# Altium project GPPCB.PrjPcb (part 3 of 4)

## Sheet Protection.SchDoc: P.C. BOARD
size A2; Revision: A; SheetNumber: 0; SheetTotal: 0
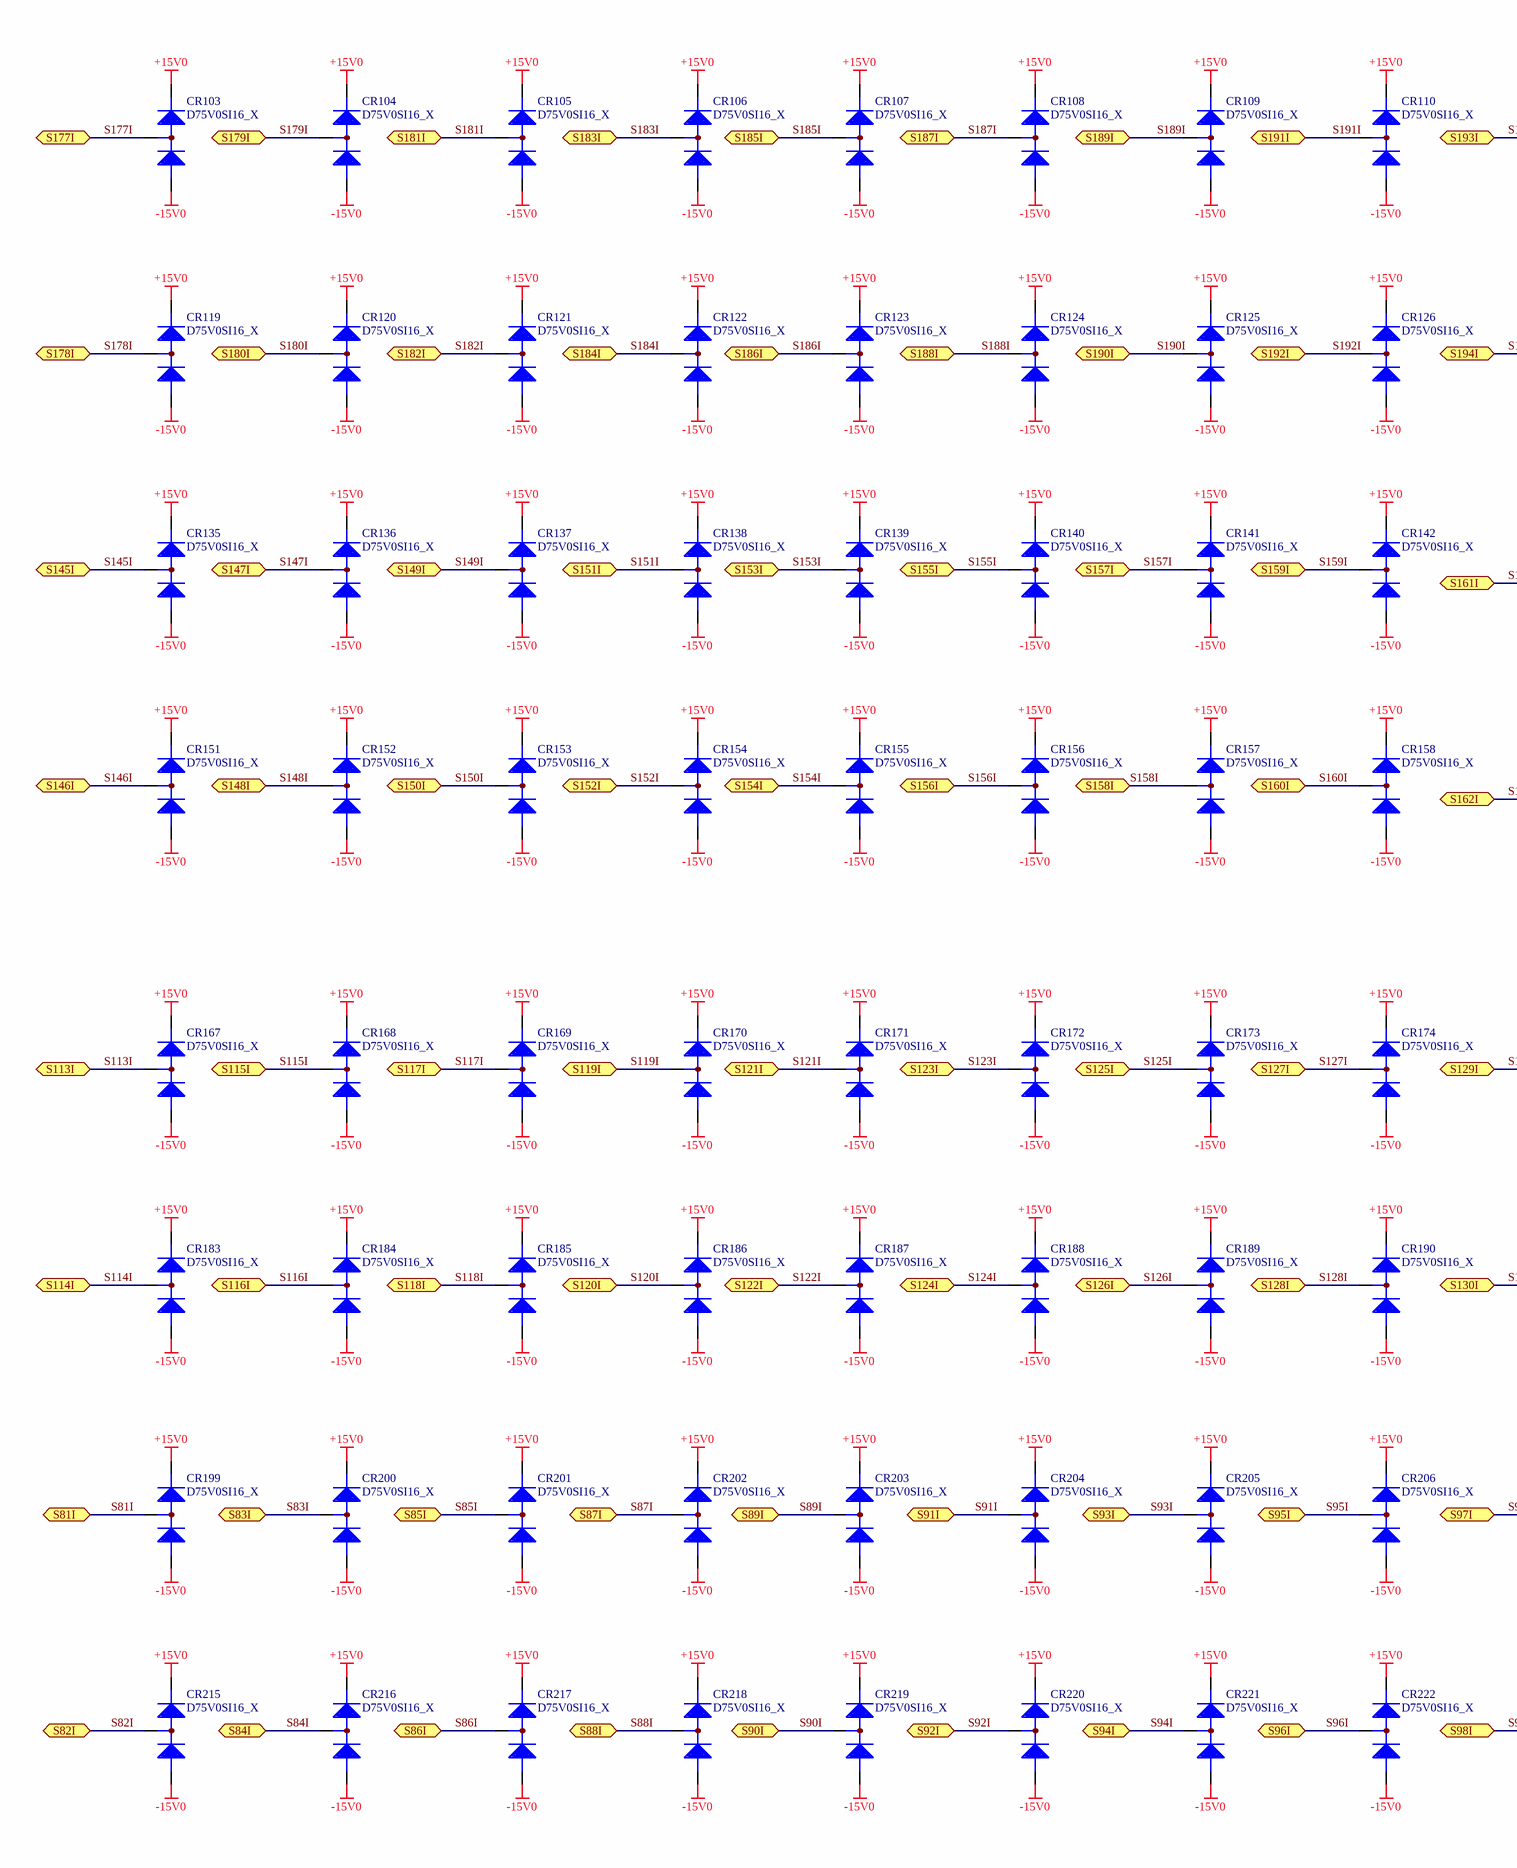
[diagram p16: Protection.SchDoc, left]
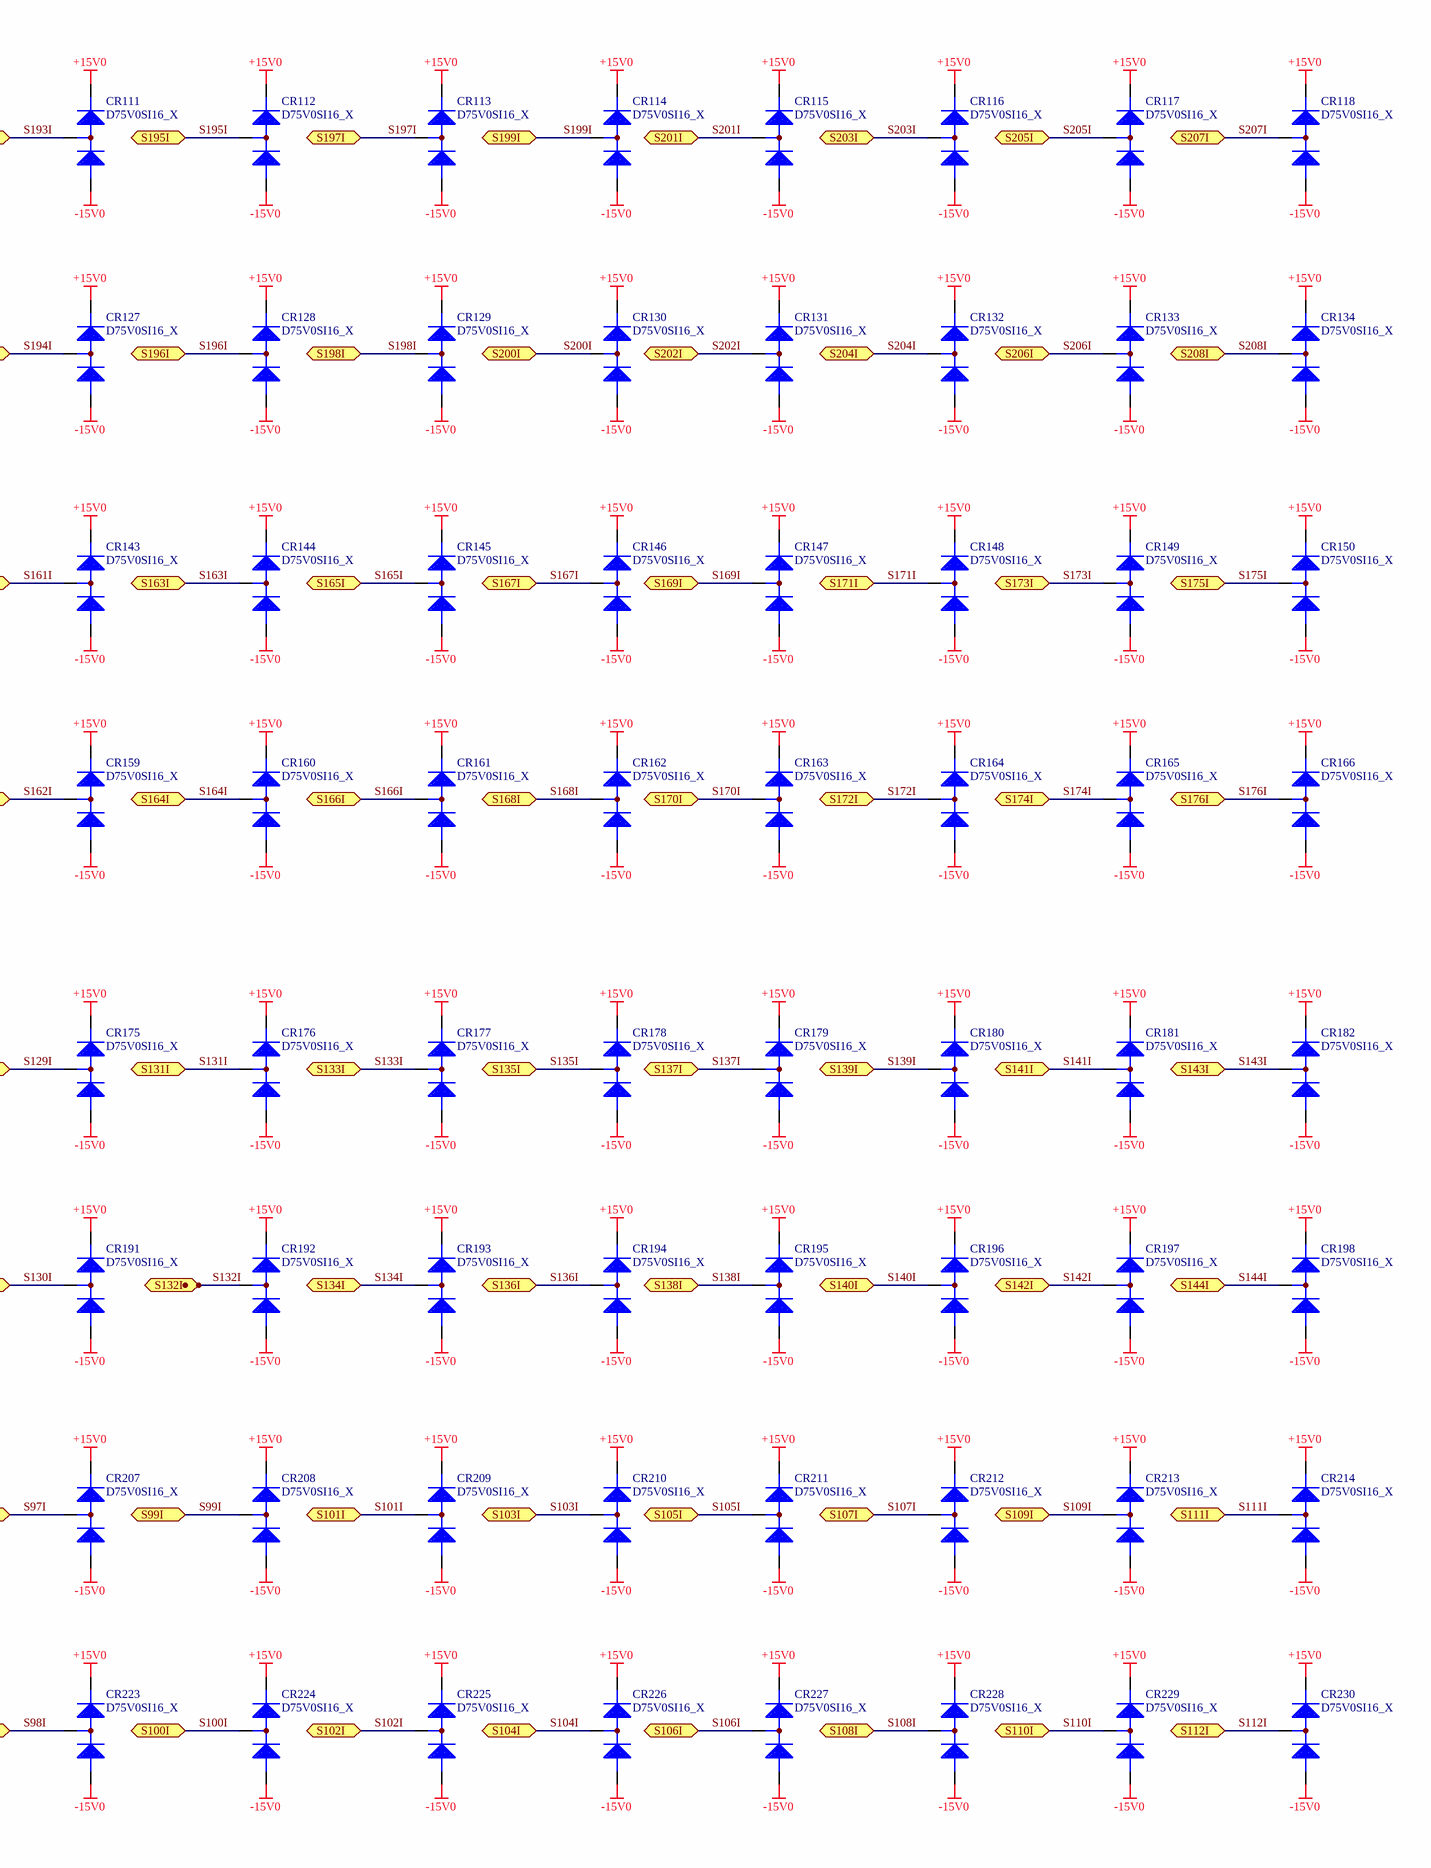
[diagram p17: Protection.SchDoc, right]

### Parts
CR103  D75V0SI16__X  [SOT-23/N]  (value not drawn)
CR104  D75V0SI16__X  [SOT-23/N]  (value not drawn)
CR105  D75V0SI16__X  [SOT-23/N]  (value not drawn)
CR106  D75V0SI16__X  [SOT-23/N]  (value not drawn)
CR107  D75V0SI16__X  [SOT-23/N]  (value not drawn)
CR108  D75V0SI16__X  [SOT-23/N]  (value not drawn)
CR109  D75V0SI16__X  [SOT-23/N]  (value not drawn)
CR110  D75V0SI16__X  [SOT-23/N]  (value not drawn)
CR111  D75V0SI16__X  [SOT-23/N]  (value not drawn)
CR112  D75V0SI16__X  [SOT-23/N]  (value not drawn)
CR113  D75V0SI16__X  [SOT-23/N]  (value not drawn)
CR114  D75V0SI16__X  [SOT-23/N]  (value not drawn)
CR115  D75V0SI16__X  [SOT-23/N]  (value not drawn)
CR116  D75V0SI16__X  [SOT-23/N]  (value not drawn)
CR117  D75V0SI16__X  [SOT-23/N]  (value not drawn)
CR118  D75V0SI16__X  [SOT-23/N]  (value not drawn)
CR119  D75V0SI16__X  [SOT-23/N]  (value not drawn)
CR120  D75V0SI16__X  [SOT-23/N]  (value not drawn)
CR121  D75V0SI16__X  [SOT-23/N]  (value not drawn)
CR122  D75V0SI16__X  [SOT-23/N]  (value not drawn)
CR123  D75V0SI16__X  [SOT-23/N]  (value not drawn)
CR124  D75V0SI16__X  [SOT-23/N]  (value not drawn)
CR125  D75V0SI16__X  [SOT-23/N]  (value not drawn)
CR126  D75V0SI16__X  [SOT-23/N]  (value not drawn)
CR127  D75V0SI16__X  [SOT-23/N]  (value not drawn)
CR128  D75V0SI16__X  [SOT-23/N]  (value not drawn)
CR129  D75V0SI16__X  [SOT-23/N]  (value not drawn)
CR130  D75V0SI16__X  [SOT-23/N]  (value not drawn)
CR131  D75V0SI16__X  [SOT-23/N]  (value not drawn)
CR132  D75V0SI16__X  [SOT-23/N]  (value not drawn)
CR133  D75V0SI16__X  [SOT-23/N]  (value not drawn)
CR134  D75V0SI16__X  [SOT-23/N]  (value not drawn)
CR135  D75V0SI16__X  [SOT-23/N]  (value not drawn)
CR136  D75V0SI16__X  [SOT-23/N]  (value not drawn)
CR137  D75V0SI16__X  [SOT-23/N]  (value not drawn)
CR138  D75V0SI16__X  [SOT-23/N]  (value not drawn)
CR139  D75V0SI16__X  [SOT-23/N]  (value not drawn)
CR140  D75V0SI16__X  [SOT-23/N]  (value not drawn)
CR141  D75V0SI16__X  [SOT-23/N]  (value not drawn)
CR142  D75V0SI16__X  [SOT-23/N]  (value not drawn)
CR143  D75V0SI16__X  [SOT-23/N]  (value not drawn)
CR144  D75V0SI16__X  [SOT-23/N]  (value not drawn)
CR145  D75V0SI16__X  [SOT-23/N]  (value not drawn)
CR146  D75V0SI16__X  [SOT-23/N]  (value not drawn)
CR147  D75V0SI16__X  [SOT-23/N]  (value not drawn)
CR148  D75V0SI16__X  [SOT-23/N]  (value not drawn)
CR149  D75V0SI16__X  [SOT-23/N]  (value not drawn)
CR150  D75V0SI16__X  [SOT-23/N]  (value not drawn)
CR151  D75V0SI16__X  [SOT-23/N]  (value not drawn)
CR152  D75V0SI16__X  [SOT-23/N]  (value not drawn)
CR153  D75V0SI16__X  [SOT-23/N]  (value not drawn)
CR154  D75V0SI16__X  [SOT-23/N]  (value not drawn)
CR155  D75V0SI16__X  [SOT-23/N]  (value not drawn)
CR156  D75V0SI16__X  [SOT-23/N]  (value not drawn)
CR157  D75V0SI16__X  [SOT-23/N]  (value not drawn)
CR158  D75V0SI16__X  [SOT-23/N]  (value not drawn)
CR159  D75V0SI16__X  [SOT-23/N]  (value not drawn)
CR160  D75V0SI16__X  [SOT-23/N]  (value not drawn)
CR161  D75V0SI16__X  [SOT-23/N]  (value not drawn)
CR162  D75V0SI16__X  [SOT-23/N]  (value not drawn)
CR163  D75V0SI16__X  [SOT-23/N]  (value not drawn)
CR164  D75V0SI16__X  [SOT-23/N]  (value not drawn)
CR165  D75V0SI16__X  [SOT-23/N]  (value not drawn)
CR166  D75V0SI16__X  [SOT-23/N]  (value not drawn)
CR167  D75V0SI16__X  [SOT-23/N]  (value not drawn)
CR168  D75V0SI16__X  [SOT-23/N]  (value not drawn)
CR169  D75V0SI16__X  [SOT-23/N]  (value not drawn)
CR170  D75V0SI16__X  [SOT-23/N]  (value not drawn)
CR171  D75V0SI16__X  [SOT-23/N]  (value not drawn)
CR172  D75V0SI16__X  [SOT-23/N]  (value not drawn)
CR173  D75V0SI16__X  [SOT-23/N]  (value not drawn)
CR174  D75V0SI16__X  [SOT-23/N]  (value not drawn)
CR175  D75V0SI16__X  [SOT-23/N]  (value not drawn)
CR176  D75V0SI16__X  [SOT-23/N]  (value not drawn)
CR177  D75V0SI16__X  [SOT-23/N]  (value not drawn)
CR178  D75V0SI16__X  [SOT-23/N]  (value not drawn)
CR179  D75V0SI16__X  [SOT-23/N]  (value not drawn)
CR180  D75V0SI16__X  [SOT-23/N]  (value not drawn)
CR181  D75V0SI16__X  [SOT-23/N]  (value not drawn)
CR182  D75V0SI16__X  [SOT-23/N]  (value not drawn)
CR183  D75V0SI16__X  [SOT-23/N]  (value not drawn)
CR184  D75V0SI16__X  [SOT-23/N]  (value not drawn)
CR185  D75V0SI16__X  [SOT-23/N]  (value not drawn)
CR186  D75V0SI16__X  [SOT-23/N]  (value not drawn)
CR187  D75V0SI16__X  [SOT-23/N]  (value not drawn)
CR188  D75V0SI16__X  [SOT-23/N]  (value not drawn)
CR189  D75V0SI16__X  [SOT-23/N]  (value not drawn)
CR190  D75V0SI16__X  [SOT-23/N]  (value not drawn)
CR191  D75V0SI16__X  [SOT-23/N]  (value not drawn)
CR192  D75V0SI16__X  [SOT-23/N]  (value not drawn)
CR193  D75V0SI16__X  [SOT-23/N]  (value not drawn)
CR194  D75V0SI16__X  [SOT-23/N]  (value not drawn)
CR195  D75V0SI16__X  [SOT-23/N]  (value not drawn)
CR196  D75V0SI16__X  [SOT-23/N]  (value not drawn)
CR197  D75V0SI16__X  [SOT-23/N]  (value not drawn)
CR198  D75V0SI16__X  [SOT-23/N]  (value not drawn)
CR199  D75V0SI16__X  [SOT-23/N]  (value not drawn)
CR200  D75V0SI16__X  [SOT-23/N]  (value not drawn)
CR201  D75V0SI16__X  [SOT-23/N]  (value not drawn)
CR202  D75V0SI16__X  [SOT-23/N]  (value not drawn)
CR203  D75V0SI16__X  [SOT-23/N]  (value not drawn)
CR204  D75V0SI16__X  [SOT-23/N]  (value not drawn)
CR205  D75V0SI16__X  [SOT-23/N]  (value not drawn)
CR206  D75V0SI16__X  [SOT-23/N]  (value not drawn)
CR207  D75V0SI16__X  [SOT-23/N]  (value not drawn)
CR208  D75V0SI16__X  [SOT-23/N]  (value not drawn)
CR209  D75V0SI16__X  [SOT-23/N]  (value not drawn)
CR210  D75V0SI16__X  [SOT-23/N]  (value not drawn)
CR211  D75V0SI16__X  [SOT-23/N]  (value not drawn)
CR212  D75V0SI16__X  [SOT-23/N]  (value not drawn)
CR213  D75V0SI16__X  [SOT-23/N]  (value not drawn)
CR214  D75V0SI16__X  [SOT-23/N]  (value not drawn)
CR215  D75V0SI16__X  [SOT-23/N]  (value not drawn)
CR216  D75V0SI16__X  [SOT-23/N]  (value not drawn)
CR217  D75V0SI16__X  [SOT-23/N]  (value not drawn)
CR218  D75V0SI16__X  [SOT-23/N]  (value not drawn)
CR219  D75V0SI16__X  [SOT-23/N]  (value not drawn)
CR220  D75V0SI16__X  [SOT-23/N]  (value not drawn)
CR221  D75V0SI16__X  [SOT-23/N]  (value not drawn)
CR222  D75V0SI16__X  [SOT-23/N]  (value not drawn)
CR223  D75V0SI16__X  [SOT-23/N]  (value not drawn)
CR224  D75V0SI16__X  [SOT-23/N]  (value not drawn)
CR225  D75V0SI16__X  [SOT-23/N]  (value not drawn)
CR226  D75V0SI16__X  [SOT-23/N]  (value not drawn)
CR227  D75V0SI16__X  [SOT-23/N]  (value not drawn)
CR228  D75V0SI16__X  [SOT-23/N]  (value not drawn)
CR229  D75V0SI16__X  [SOT-23/N]  (value not drawn)
CR230  D75V0SI16__X  [SOT-23/N]  (value not drawn)

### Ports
S81I (bidir), S82I (bidir), S83I (bidir), S84I (bidir), S85I (bidir), S86I (bidir), S87I (bidir), S88I (bidir), S89I (bidir), S90I (bidir), S91I (bidir), S92I (bidir), S93I (bidir), S94I (bidir), S95I (bidir), S96I (bidir), S97I (bidir), S98I (bidir), S99I (bidir), S100I (bidir), S101I (bidir), S102I (bidir), S103I (bidir), S104I (bidir), S105I (bidir), S106I (bidir), S107I (bidir), S108I (bidir), S109I (bidir), S110I (bidir), S111I (bidir), S112I (bidir), S113I (bidir), S114I (bidir), S115I (bidir), S116I (bidir), S117I (bidir), S118I (bidir), S119I (bidir), S120I (bidir), S121I (bidir), S122I (bidir), S123I (bidir), S124I (bidir), S125I (bidir), S126I (bidir), S127I (bidir), S128I (bidir), S129I (bidir), S130I (bidir), S131I (bidir), S132I (bidir), S133I (bidir), S134I (bidir), S135I (bidir), S136I (bidir), S137I (bidir), S138I (bidir), S139I (bidir), S140I (bidir), S141I (bidir), S142I (bidir), S143I (bidir), S144I (bidir), S145I (bidir), S146I (bidir), S147I (bidir), S148I (bidir), S149I (bidir), S150I (bidir), S151I (bidir), S152I (bidir), S153I (bidir), S154I (bidir), S155I (bidir), S156I (bidir), S157I (bidir), S158I (bidir), S159I (bidir), S160I (bidir), S161I (bidir), S162I (bidir), S163I (bidir), S164I (bidir), S165I (bidir), S166I (bidir), S167I (bidir), S168I (bidir), S169I (bidir), S170I (bidir), S171I (bidir), S172I (bidir), S173I (bidir), S174I (bidir), S175I (bidir), S176I (bidir), S177I (bidir), S178I (bidir), S179I (bidir), S180I (bidir), S181I (bidir), S182I (bidir), S183I (bidir), S184I (bidir), S185I (bidir), S186I (bidir), S187I (bidir), S188I (bidir), S189I (bidir), S190I (bidir), S191I (bidir), S192I (bidir), S193I (bidir), S194I (bidir), S195I (bidir), S196I (bidir), S197I (bidir), S198I (bidir), S199I (bidir), S200I (bidir), S201I (bidir), S202I (bidir), S203I (bidir), S204I (bidir), S205I (bidir), S206I (bidir), S207I (bidir), S208I (bidir)

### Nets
+15V0: CR103.2(K) CR104.2(K) CR105.2(K) CR106.2(K) CR107.2(K) CR108.2(K) CR109.2(K) CR110.2(K) CR111.2(K) CR112.2(K) CR113.2(K) CR114.2(K) CR115.2(K) CR116.2(K) CR117.2(K) CR118.2(K) CR119.2(K) CR120.2(K) CR121.2(K) CR122.2(K) CR123.2(K) CR124.2(K) CR125.2(K) CR126.2(K) CR127.2(K) CR128.2(K) CR129.2(K) CR130.2(K) CR131.2(K) CR132.2(K) CR133.2(K) CR134.2(K) CR135.2(K) CR136.2(K) CR137.2(K) CR138.2(K) CR139.2(K) CR140.2(K) CR141.2(K) CR142.2(K) CR143.2(K) CR144.2(K) CR145.2(K) CR146.2(K) CR147.2(K) CR148.2(K) CR149.2(K) CR150.2(K) CR151.2(K) CR152.2(K) CR153.2(K) CR154.2(K) CR155.2(K) CR156.2(K) CR157.2(K) CR158.2(K) CR159.2(K) CR160.2(K) CR161.2(K) CR162.2(K) CR163.2(K) CR164.2(K) CR165.2(K) CR166.2(K) CR167.2(K) CR168.2(K) CR169.2(K) CR170.2(K) CR171.2(K) CR172.2(K) CR173.2(K) CR174.2(K) CR175.2(K) CR176.2(K) CR177.2(K) CR178.2(K) CR179.2(K) CR180.2(K) CR181.2(K) CR182.2(K) CR183.2(K) CR184.2(K) CR185.2(K) CR186.2(K) CR187.2(K) CR188.2(K) CR189.2(K) CR190.2(K) CR191.2(K) CR192.2(K) CR193.2(K) CR194.2(K) CR195.2(K) CR196.2(K) CR197.2(K) CR198.2(K) CR199.2(K) CR200.2(K) CR201.2(K) CR202.2(K) CR203.2(K) CR204.2(K) CR205.2(K) CR206.2(K) CR207.2(K) CR208.2(K) CR209.2(K) CR210.2(K) CR211.2(K) CR212.2(K) CR213.2(K) CR214.2(K) CR215.2(K) CR216.2(K) CR217.2(K) CR218.2(K) CR219.2(K) CR220.2(K) CR221.2(K) CR222.2(K) CR223.2(K) CR224.2(K) CR225.2(K) CR226.2(K) CR227.2(K) CR228.2(K) CR229.2(K) CR230.2(K)
-15V0: CR103.1(A) CR104.1(A) CR105.1(A) CR106.1(A) CR107.1(A) CR108.1(A) CR109.1(A) CR110.1(A) CR111.1(A) CR112.1(A) CR113.1(A) CR114.1(A) CR115.1(A) CR116.1(A) CR117.1(A) CR118.1(A) CR119.1(A) CR120.1(A) CR121.1(A) CR122.1(A) CR123.1(A) CR124.1(A) CR125.1(A) CR126.1(A) CR127.1(A) CR128.1(A) CR129.1(A) CR130.1(A) CR131.1(A) CR132.1(A) CR133.1(A) CR134.1(A) CR135.1(A) CR136.1(A) CR137.1(A) CR138.1(A) CR139.1(A) CR140.1(A) CR141.1(A) CR142.1(A) CR143.1(A) CR144.1(A) CR145.1(A) CR146.1(A) CR147.1(A) CR148.1(A) CR149.1(A) CR150.1(A) CR151.1(A) CR152.1(A) CR153.1(A) CR154.1(A) CR155.1(A) CR156.1(A) CR157.1(A) CR158.1(A) CR159.1(A) CR160.1(A) CR161.1(A) CR162.1(A) CR163.1(A) CR164.1(A) CR165.1(A) CR166.1(A) CR167.1(A) CR168.1(A) CR169.1(A) CR170.1(A) CR171.1(A) CR172.1(A) CR173.1(A) CR174.1(A) CR175.1(A) CR176.1(A) CR177.1(A) CR178.1(A) CR179.1(A) CR180.1(A) CR181.1(A) CR182.1(A) CR183.1(A) CR184.1(A) CR185.1(A) CR186.1(A) CR187.1(A) CR188.1(A) CR189.1(A) CR190.1(A) CR191.1(A) CR192.1(A) CR193.1(A) CR194.1(A) CR195.1(A) CR196.1(A) CR197.1(A) CR198.1(A) CR199.1(A) CR200.1(A) CR201.1(A) CR202.1(A) CR203.1(A) CR204.1(A) CR205.1(A) CR206.1(A) CR207.1(A) CR208.1(A) CR209.1(A) CR210.1(A) CR211.1(A) CR212.1(A) CR213.1(A) CR214.1(A) CR215.1(A) CR216.1(A) CR217.1(A) CR218.1(A) CR219.1(A) CR220.1(A) CR221.1(A) CR222.1(A) CR223.1(A) CR224.1(A) CR225.1(A) CR226.1(A) CR227.1(A) CR228.1(A) CR229.1(A) CR230.1(A)
S81I: CR199.3(KA) ; port S81I
S82I: CR215.3(KA) ; port S82I
S83I: CR200.3(KA) ; port S83I
S84I: CR216.3(KA) ; port S84I
S85I: CR201.3(KA) ; port S85I
S86I: CR217.3(KA) ; port S86I
S87I: CR202.3(KA) ; port S87I
S88I: CR218.3(KA) ; port S88I
S89I: CR203.3(KA) ; port S89I
S90I: CR219.3(KA) ; port S90I
S91I: CR204.3(KA) ; port S91I
S92I: CR220.3(KA) ; port S92I
S93I: CR205.3(KA) ; port S93I
S94I: CR221.3(KA) ; port S94I
S95I: CR206.3(KA) ; port S95I
S96I: CR222.3(KA) ; port S96I
S97I: CR207.3(KA) ; port S97I
S98I: CR223.3(KA) ; port S98I
S99I: CR208.3(KA) ; port S99I
S100I: CR224.3(KA) ; port S100I
S101I: CR209.3(KA) ; port S101I
S102I: CR225.3(KA) ; port S102I
S103I: CR210.3(KA) ; port S103I
S104I: CR226.3(KA) ; port S104I
S105I: CR211.3(KA) ; port S105I
S106I: CR227.3(KA) ; port S106I
S107I: CR212.3(KA) ; port S107I
S108I: CR228.3(KA) ; port S108I
S109I: CR213.3(KA) ; port S109I
S110I: CR229.3(KA) ; port S110I
S111I: CR214.3(KA) ; port S111I
S112I: CR230.3(KA) ; port S112I
S113I: CR167.3(KA) ; port S113I
S114I: CR183.3(KA) ; port S114I
S115I: CR168.3(KA) ; port S115I
S116I: CR184.3(KA) ; port S116I
S117I: CR169.3(KA) ; port S117I
S118I: CR185.3(KA) ; port S118I
S119I: CR170.3(KA) ; port S119I
S120I: CR186.3(KA) ; port S120I
S121I: CR171.3(KA) ; port S121I
S122I: CR187.3(KA) ; port S122I
S123I: CR172.3(KA) ; port S123I
S124I: CR188.3(KA) ; port S124I
S125I: CR173.3(KA) ; port S125I
S126I: CR189.3(KA) ; port S126I
S127I: CR174.3(KA) ; port S127I
S128I: CR190.3(KA) ; port S128I
S129I: CR175.3(KA) ; port S129I
S130I: CR191.3(KA) ; port S130I
S131I: CR176.3(KA) ; port S131I
S132I: CR192.3(KA) ; port S132I
S133I: CR177.3(KA) ; port S133I
S134I: CR193.3(KA) ; port S134I
S135I: CR178.3(KA) ; port S135I
S136I: CR194.3(KA) ; port S136I
S137I: CR179.3(KA) ; port S137I
S138I: CR195.3(KA) ; port S138I
S139I: CR180.3(KA) ; port S139I
S140I: CR196.3(KA) ; port S140I
S141I: CR181.3(KA) ; port S141I
S142I: CR197.3(KA) ; port S142I
S143I: CR182.3(KA) ; port S143I
S144I: CR198.3(KA) ; port S144I
S145I: CR135.3(KA) ; port S145I
S146I: CR151.3(KA) ; port S146I
S147I: CR136.3(KA) ; port S147I
S148I: CR152.3(KA) ; port S148I
S149I: CR137.3(KA) ; port S149I
S150I: CR153.3(KA) ; port S150I
S151I: CR138.3(KA) ; port S151I
S152I: CR154.3(KA) ; port S152I
S153I: CR139.3(KA) ; port S153I
S154I: CR155.3(KA) ; port S154I
S155I: CR140.3(KA) ; port S155I
S156I: CR156.3(KA) ; port S156I
S157I: CR141.3(KA) ; port S157I
S158I: CR157.3(KA) ; port S158I
S159I: CR142.3(KA) ; port S159I
S160I: CR158.3(KA) ; port S160I
S161I: CR143.3(KA) ; port S161I
S162I: CR159.3(KA) ; port S162I
S163I: CR144.3(KA) ; port S163I
S164I: CR160.3(KA) ; port S164I
S165I: CR145.3(KA) ; port S165I
S166I: CR161.3(KA) ; port S166I
S167I: CR146.3(KA) ; port S167I
S168I: CR162.3(KA) ; port S168I
S169I: CR147.3(KA) ; port S169I
S170I: CR163.3(KA) ; port S170I
S171I: CR148.3(KA) ; port S171I
S172I: CR164.3(KA) ; port S172I
S173I: CR149.3(KA) ; port S173I
S174I: CR165.3(KA) ; port S174I
S175I: CR150.3(KA) ; port S175I
S176I: CR166.3(KA) ; port S176I
S177I: CR103.3(KA) ; port S177I
S178I: CR119.3(KA) ; port S178I
S179I: CR104.3(KA) ; port S179I
S180I: CR120.3(KA) ; port S180I
S181I: CR105.3(KA) ; port S181I
S182I: CR121.3(KA) ; port S182I
S183I: CR106.3(KA) ; port S183I
S184I: CR122.3(KA) ; port S184I
S185I: CR107.3(KA) ; port S185I
S186I: CR123.3(KA) ; port S186I
S187I: CR108.3(KA) ; port S187I
S188I: CR124.3(KA) ; port S188I
S189I: CR109.3(KA) ; port S189I
S190I: CR125.3(KA) ; port S190I
S191I: CR110.3(KA) ; port S191I
S192I: CR126.3(KA) ; port S192I
S193I: CR111.3(KA) ; port S193I
S194I: CR127.3(KA) ; port S194I
S195I: CR112.3(KA) ; port S195I
S196I: CR128.3(KA) ; port S196I
S197I: CR113.3(KA) ; port S197I
S198I: CR129.3(KA) ; port S198I
S199I: CR114.3(KA) ; port S199I
S200I: CR130.3(KA) ; port S200I
S201I: CR115.3(KA) ; port S201I
S202I: CR131.3(KA) ; port S202I
S203I: CR116.3(KA) ; port S203I
S204I: CR132.3(KA) ; port S204I
S205I: CR117.3(KA) ; port S205I
S206I: CR133.3(KA) ; port S206I
S207I: CR118.3(KA) ; port S207I
S208I: CR134.3(KA) ; port S208I

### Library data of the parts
CR103-CR230 = D75V0SI16__X: DIODE,  DUAL, SERIES PAIR, 75V; CHECKER: GRL 5/19/03; DESIGNER: GTN 5/18/03; AREA: 0.0293; TYPE: DIODE_X

## Sheet Protection1.SchDoc: P.C. BOARD
size A2; Revision: A; SheetNumber: 0; SheetTotal: 0
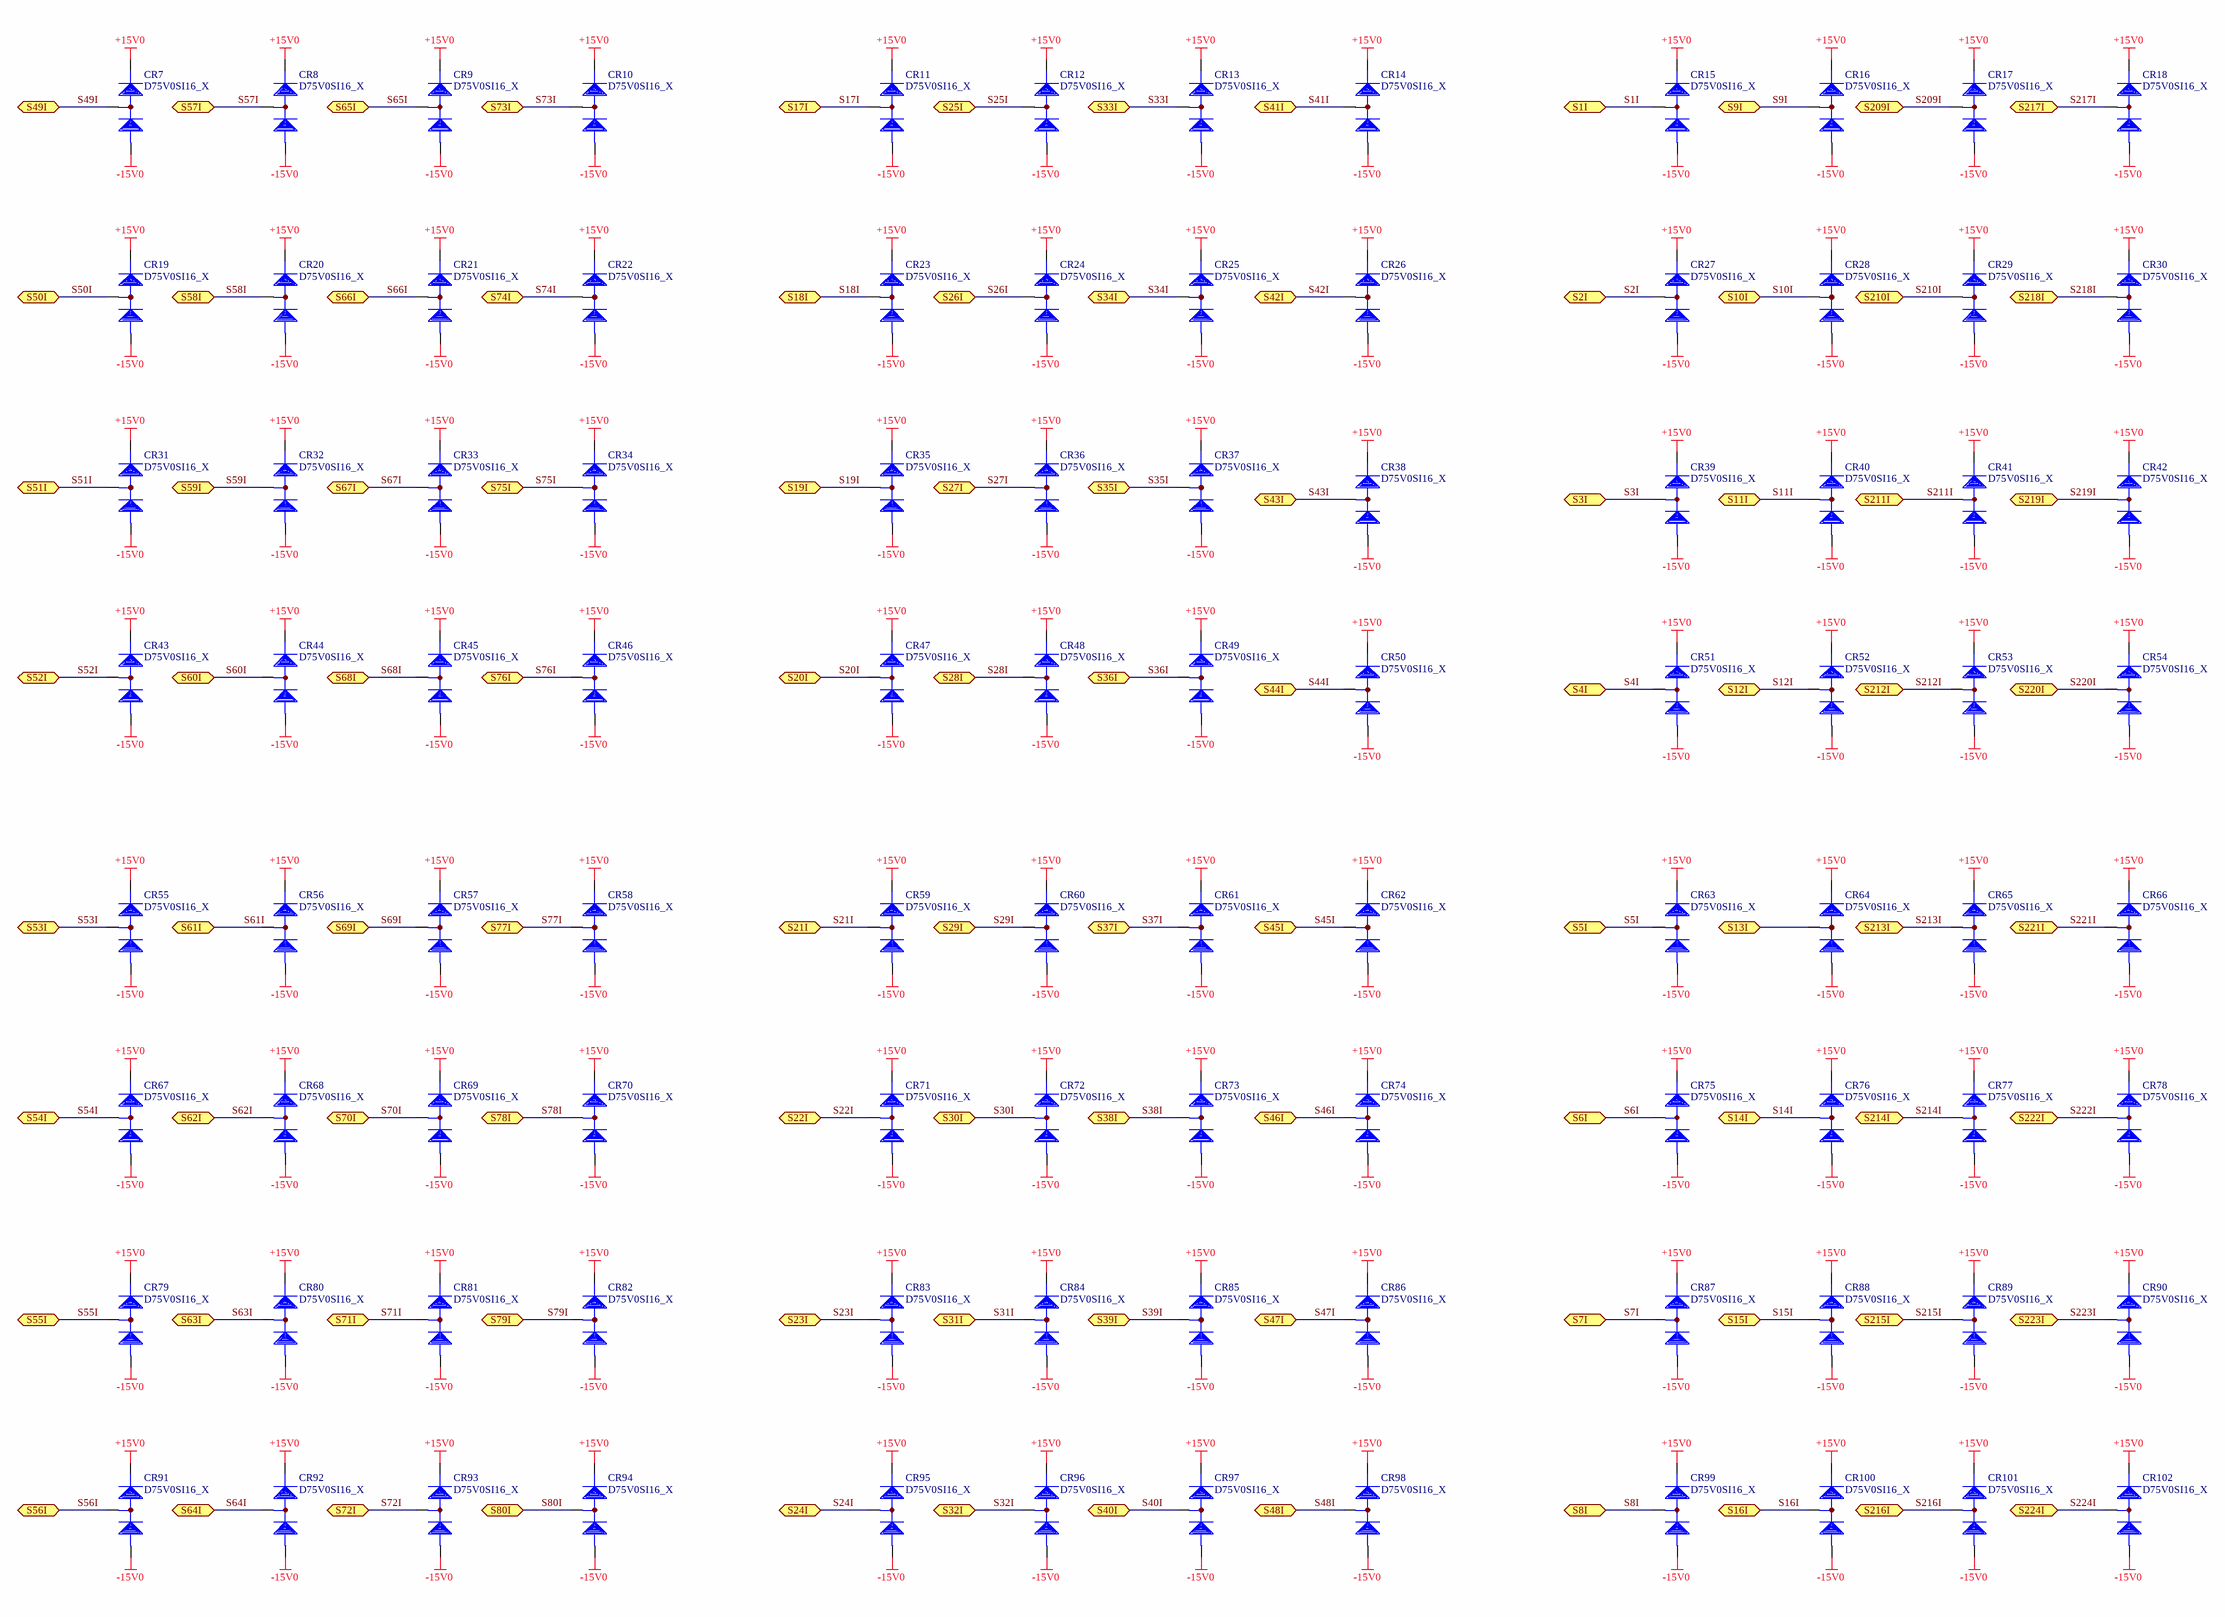
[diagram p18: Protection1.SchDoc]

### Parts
CR7  D75V0SI16__X  [SOT-23/N]  (value not drawn)
CR8  D75V0SI16__X  [SOT-23/N]  (value not drawn)
CR9  D75V0SI16__X  [SOT-23/N]  (value not drawn)
CR10  D75V0SI16__X  [SOT-23/N]  (value not drawn)
CR11  D75V0SI16__X  [SOT-23/N]  (value not drawn)
CR12  D75V0SI16__X  [SOT-23/N]  (value not drawn)
CR13  D75V0SI16__X  [SOT-23/N]  (value not drawn)
CR14  D75V0SI16__X  [SOT-23/N]  (value not drawn)
CR15  D75V0SI16__X  [SOT-23/N]  (value not drawn)
CR16  D75V0SI16__X  [SOT-23/N]  (value not drawn)
CR17  D75V0SI16__X  [SOT-23/N]  (value not drawn)
CR18  D75V0SI16__X  [SOT-23/N]  (value not drawn)
CR19  D75V0SI16__X  [SOT-23/N]  (value not drawn)
CR20  D75V0SI16__X  [SOT-23/N]  (value not drawn)
CR21  D75V0SI16__X  [SOT-23/N]  (value not drawn)
CR22  D75V0SI16__X  [SOT-23/N]  (value not drawn)
CR23  D75V0SI16__X  [SOT-23/N]  (value not drawn)
CR24  D75V0SI16__X  [SOT-23/N]  (value not drawn)
CR25  D75V0SI16__X  [SOT-23/N]  (value not drawn)
CR26  D75V0SI16__X  [SOT-23/N]  (value not drawn)
CR27  D75V0SI16__X  [SOT-23/N]  (value not drawn)
CR28  D75V0SI16__X  [SOT-23/N]  (value not drawn)
CR29  D75V0SI16__X  [SOT-23/N]  (value not drawn)
CR30  D75V0SI16__X  [SOT-23/N]  (value not drawn)
CR31  D75V0SI16__X  [SOT-23/N]  (value not drawn)
CR32  D75V0SI16__X  [SOT-23/N]  (value not drawn)
CR33  D75V0SI16__X  [SOT-23/N]  (value not drawn)
CR34  D75V0SI16__X  [SOT-23/N]  (value not drawn)
CR35  D75V0SI16__X  [SOT-23/N]  (value not drawn)
CR36  D75V0SI16__X  [SOT-23/N]  (value not drawn)
CR37  D75V0SI16__X  [SOT-23/N]  (value not drawn)
CR38  D75V0SI16__X  [SOT-23/N]  (value not drawn)
CR39  D75V0SI16__X  [SOT-23/N]  (value not drawn)
CR40  D75V0SI16__X  [SOT-23/N]  (value not drawn)
CR41  D75V0SI16__X  [SOT-23/N]  (value not drawn)
CR42  D75V0SI16__X  [SOT-23/N]  (value not drawn)
CR43  D75V0SI16__X  [SOT-23/N]  (value not drawn)
CR44  D75V0SI16__X  [SOT-23/N]  (value not drawn)
CR45  D75V0SI16__X  [SOT-23/N]  (value not drawn)
CR46  D75V0SI16__X  [SOT-23/N]  (value not drawn)
CR47  D75V0SI16__X  [SOT-23/N]  (value not drawn)
CR48  D75V0SI16__X  [SOT-23/N]  (value not drawn)
CR49  D75V0SI16__X  [SOT-23/N]  (value not drawn)
CR50  D75V0SI16__X  [SOT-23/N]  (value not drawn)
CR51  D75V0SI16__X  [SOT-23/N]  (value not drawn)
CR52  D75V0SI16__X  [SOT-23/N]  (value not drawn)
CR53  D75V0SI16__X  [SOT-23/N]  (value not drawn)
CR54  D75V0SI16__X  [SOT-23/N]  (value not drawn)
CR55  D75V0SI16__X  [SOT-23/N]  (value not drawn)
CR56  D75V0SI16__X  [SOT-23/N]  (value not drawn)
CR57  D75V0SI16__X  [SOT-23/N]  (value not drawn)
CR58  D75V0SI16__X  [SOT-23/N]  (value not drawn)
CR59  D75V0SI16__X  [SOT-23/N]  (value not drawn)
CR60  D75V0SI16__X  [SOT-23/N]  (value not drawn)
CR61  D75V0SI16__X  [SOT-23/N]  (value not drawn)
CR62  D75V0SI16__X  [SOT-23/N]  (value not drawn)
CR63  D75V0SI16__X  [SOT-23/N]  (value not drawn)
CR64  D75V0SI16__X  [SOT-23/N]  (value not drawn)
CR65  D75V0SI16__X  [SOT-23/N]  (value not drawn)
CR66  D75V0SI16__X  [SOT-23/N]  (value not drawn)
CR67  D75V0SI16__X  [SOT-23/N]  (value not drawn)
CR68  D75V0SI16__X  [SOT-23/N]  (value not drawn)
CR69  D75V0SI16__X  [SOT-23/N]  (value not drawn)
CR70  D75V0SI16__X  [SOT-23/N]  (value not drawn)
CR71  D75V0SI16__X  [SOT-23/N]  (value not drawn)
CR72  D75V0SI16__X  [SOT-23/N]  (value not drawn)
CR73  D75V0SI16__X  [SOT-23/N]  (value not drawn)
CR74  D75V0SI16__X  [SOT-23/N]  (value not drawn)
CR75  D75V0SI16__X  [SOT-23/N]  (value not drawn)
CR76  D75V0SI16__X  [SOT-23/N]  (value not drawn)
CR77  D75V0SI16__X  [SOT-23/N]  (value not drawn)
CR78  D75V0SI16__X  [SOT-23/N]  (value not drawn)
CR79  D75V0SI16__X  [SOT-23/N]  (value not drawn)
CR80  D75V0SI16__X  [SOT-23/N]  (value not drawn)
CR81  D75V0SI16__X  [SOT-23/N]  (value not drawn)
CR82  D75V0SI16__X  [SOT-23/N]  (value not drawn)
CR83  D75V0SI16__X  [SOT-23/N]  (value not drawn)
CR84  D75V0SI16__X  [SOT-23/N]  (value not drawn)
CR85  D75V0SI16__X  [SOT-23/N]  (value not drawn)
CR86  D75V0SI16__X  [SOT-23/N]  (value not drawn)
CR87  D75V0SI16__X  [SOT-23/N]  (value not drawn)
CR88  D75V0SI16__X  [SOT-23/N]  (value not drawn)
CR89  D75V0SI16__X  [SOT-23/N]  (value not drawn)
CR90  D75V0SI16__X  [SOT-23/N]  (value not drawn)
CR91  D75V0SI16__X  [SOT-23/N]  (value not drawn)
CR92  D75V0SI16__X  [SOT-23/N]  (value not drawn)
CR93  D75V0SI16__X  [SOT-23/N]  (value not drawn)
CR94  D75V0SI16__X  [SOT-23/N]  (value not drawn)
CR95  D75V0SI16__X  [SOT-23/N]  (value not drawn)
CR96  D75V0SI16__X  [SOT-23/N]  (value not drawn)
CR97  D75V0SI16__X  [SOT-23/N]  (value not drawn)
CR98  D75V0SI16__X  [SOT-23/N]  (value not drawn)
CR99  D75V0SI16__X  [SOT-23/N]  (value not drawn)
CR100  D75V0SI16__X  [SOT-23/N]  (value not drawn)
CR101  D75V0SI16__X  [SOT-23/N]  (value not drawn)
CR102  D75V0SI16__X  [SOT-23/N]  (value not drawn)

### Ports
S1I (bidir), S2I (bidir), S3I (bidir), S4I (bidir), S5I (bidir), S6I (bidir), S7I (bidir), S8I (bidir), S9I (bidir), S10I (bidir), S11I (bidir), S12I (bidir), S13I (bidir), S14I (bidir), S15I (bidir), S16I (bidir), S17I (bidir), S18I (bidir), S19I (bidir), S20I (bidir), S21I (bidir), S22I (bidir), S23I (bidir), S24I (bidir), S25I (bidir), S26I (bidir), S27I (bidir), S28I (bidir), S29I (bidir), S30I (bidir), S31I (bidir), S32I (bidir), S33I (bidir), S34I (bidir), S35I (bidir), S36I (bidir), S37I (bidir), S38I (bidir), S39I (bidir), S40I (bidir), S41I (bidir), S42I (bidir), S43I (bidir), S44I (bidir), S45I (bidir), S46I (bidir), S47I (bidir), S48I (bidir), S49I (bidir), S50I (bidir), S51I (bidir), S52I (bidir), S53I (bidir), S54I (bidir), S55I (bidir), S56I (bidir), S57I (bidir), S58I (bidir), S59I (bidir), S60I (bidir), S61I (bidir), S62I (bidir), S63I (bidir), S64I (bidir), S65I (bidir), S66I (bidir), S67I (bidir), S68I (bidir), S69I (bidir), S70I (bidir), S71I (bidir), S72I (bidir), S73I (bidir), S74I (bidir), S75I (bidir), S76I (bidir), S77I (bidir), S78I (bidir), S79I (bidir), S80I (bidir), S209I (bidir), S210I (bidir), S211I (bidir), S212I (bidir), S213I (bidir), S214I (bidir), S215I (bidir), S216I (bidir), S217I (bidir), S218I (bidir), S219I (bidir), S220I (bidir), S221I (bidir), S222I (bidir), S223I (bidir), S224I (bidir)

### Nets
+15V0: CR7.2(K) CR8.2(K) CR9.2(K) CR10.2(K) CR11.2(K) CR12.2(K) CR13.2(K) CR14.2(K) CR15.2(K) CR16.2(K) CR17.2(K) CR18.2(K) CR19.2(K) CR20.2(K) CR21.2(K) CR22.2(K) CR23.2(K) CR24.2(K) CR25.2(K) CR26.2(K) CR27.2(K) CR28.2(K) CR29.2(K) CR30.2(K) CR31.2(K) CR32.2(K) CR33.2(K) CR34.2(K) CR35.2(K) CR36.2(K) CR37.2(K) CR38.2(K) CR39.2(K) CR40.2(K) CR41.2(K) CR42.2(K) CR43.2(K) CR44.2(K) CR45.2(K) CR46.2(K) CR47.2(K) CR48.2(K) CR49.2(K) CR50.2(K) CR51.2(K) CR52.2(K) CR53.2(K) CR54.2(K) CR55.2(K) CR56.2(K) CR57.2(K) CR58.2(K) CR59.2(K) CR60.2(K) CR61.2(K) CR62.2(K) CR63.2(K) CR64.2(K) CR65.2(K) CR66.2(K) CR67.2(K) CR68.2(K) CR69.2(K) CR70.2(K) CR71.2(K) CR72.2(K) CR73.2(K) CR74.2(K) CR75.2(K) CR76.2(K) CR77.2(K) CR78.2(K) CR79.2(K) CR80.2(K) CR81.2(K) CR82.2(K) CR83.2(K) CR84.2(K) CR85.2(K) CR86.2(K) CR87.2(K) CR88.2(K) CR89.2(K) CR90.2(K) CR91.2(K) CR92.2(K) CR93.2(K) CR94.2(K) CR95.2(K) CR96.2(K) CR97.2(K) CR98.2(K) CR99.2(K) CR100.2(K) CR101.2(K) CR102.2(K)
-15V0: CR7.1(A) CR8.1(A) CR9.1(A) CR10.1(A) CR11.1(A) CR12.1(A) CR13.1(A) CR14.1(A) CR15.1(A) CR16.1(A) CR17.1(A) CR18.1(A) CR19.1(A) CR20.1(A) CR21.1(A) CR22.1(A) CR23.1(A) CR24.1(A) CR25.1(A) CR26.1(A) CR27.1(A) CR28.1(A) CR29.1(A) CR30.1(A) CR31.1(A) CR32.1(A) CR33.1(A) CR34.1(A) CR35.1(A) CR36.1(A) CR37.1(A) CR38.1(A) CR39.1(A) CR40.1(A) CR41.1(A) CR42.1(A) CR43.1(A) CR44.1(A) CR45.1(A) CR46.1(A) CR47.1(A) CR48.1(A) CR49.1(A) CR50.1(A) CR51.1(A) CR52.1(A) CR53.1(A) CR54.1(A) CR55.1(A) CR56.1(A) CR57.1(A) CR58.1(A) CR59.1(A) CR60.1(A) CR61.1(A) CR62.1(A) CR63.1(A) CR64.1(A) CR65.1(A) CR66.1(A) CR67.1(A) CR68.1(A) CR69.1(A) CR70.1(A) CR71.1(A) CR72.1(A) CR73.1(A) CR74.1(A) CR75.1(A) CR76.1(A) CR77.1(A) CR78.1(A) CR79.1(A) CR80.1(A) CR81.1(A) CR82.1(A) CR83.1(A) CR84.1(A) CR85.1(A) CR86.1(A) CR87.1(A) CR88.1(A) CR89.1(A) CR90.1(A) CR91.1(A) CR92.1(A) CR93.1(A) CR94.1(A) CR95.1(A) CR96.1(A) CR97.1(A) CR98.1(A) CR99.1(A) CR100.1(A) CR101.1(A) CR102.1(A)
S1I: CR15.3(KA) ; port S1I
S2I: CR27.3(KA) ; port S2I
S3I: CR39.3(KA) ; port S3I
S4I: CR51.3(KA) ; port S4I
S5I: CR63.3(KA) ; port S5I
S6I: CR75.3(KA) ; port S6I
S7I: CR87.3(KA) ; port S7I
S8I: CR99.3(KA) ; port S8I
S9I: CR16.3(KA) ; port S9I
S10I: CR28.3(KA) ; port S10I
S11I: CR40.3(KA) ; port S11I
S12I: CR52.3(KA) ; port S12I
S13I: CR64.3(KA) ; port S13I
S14I: CR76.3(KA) ; port S14I
S15I: CR88.3(KA) ; port S15I
S16I: CR100.3(KA) ; port S16I
S17I: CR11.3(KA) ; port S17I
S18I: CR23.3(KA) ; port S18I
S19I: CR35.3(KA) ; port S19I
S20I: CR47.3(KA) ; port S20I
S21I: CR59.3(KA) ; port S21I
S22I: CR71.3(KA) ; port S22I
S23I: CR83.3(KA) ; port S23I
S24I: CR95.3(KA) ; port S24I
S25I: CR12.3(KA) ; port S25I
S26I: CR24.3(KA) ; port S26I
S27I: CR36.3(KA) ; port S27I
S28I: CR48.3(KA) ; port S28I
S29I: CR60.3(KA) ; port S29I
S30I: CR72.3(KA) ; port S30I
S31I: CR84.3(KA) ; port S31I
S32I: CR96.3(KA) ; port S32I
S33I: CR13.3(KA) ; port S33I
S34I: CR25.3(KA) ; port S34I
S35I: CR37.3(KA) ; port S35I
S36I: CR49.3(KA) ; port S36I
S37I: CR61.3(KA) ; port S37I
S38I: CR73.3(KA) ; port S38I
S39I: CR85.3(KA) ; port S39I
S40I: CR97.3(KA) ; port S40I
S41I: CR14.3(KA) ; port S41I
S42I: CR26.3(KA) ; port S42I
S43I: CR38.3(KA) ; port S43I
S44I: CR50.3(KA) ; port S44I
S45I: CR62.3(KA) ; port S45I
S46I: CR74.3(KA) ; port S46I
S47I: CR86.3(KA) ; port S47I
S48I: CR98.3(KA) ; port S48I
S49I: CR7.3(KA) ; port S49I
S50I: CR19.3(KA) ; port S50I
S51I: CR31.3(KA) ; port S51I
S52I: CR43.3(KA) ; port S52I
S53I: CR55.3(KA) ; port S53I
S54I: CR67.3(KA) ; port S54I
S55I: CR79.3(KA) ; port S55I
S56I: CR91.3(KA) ; port S56I
S57I: CR8.3(KA) ; port S57I
S58I: CR20.3(KA) ; port S58I
S59I: CR32.3(KA) ; port S59I
S60I: CR44.3(KA) ; port S60I
S61I: CR56.3(KA) ; port S61I
S62I: CR68.3(KA) ; port S62I
S63I: CR80.3(KA) ; port S63I
S64I: CR92.3(KA) ; port S64I
S65I: CR9.3(KA) ; port S65I
S66I: CR21.3(KA) ; port S66I
S67I: CR33.3(KA) ; port S67I
S68I: CR45.3(KA) ; port S68I
S69I: CR57.3(KA) ; port S69I
S70I: CR69.3(KA) ; port S70I
S71I: CR81.3(KA) ; port S71I
S72I: CR93.3(KA) ; port S72I
S73I: CR10.3(KA) ; port S73I
S74I: CR22.3(KA) ; port S74I
S75I: CR34.3(KA) ; port S75I
S76I: CR46.3(KA) ; port S76I
S77I: CR58.3(KA) ; port S77I
S78I: CR70.3(KA) ; port S78I
S79I: CR82.3(KA) ; port S79I
S80I: CR94.3(KA) ; port S80I
S209I: CR17.3(KA) ; port S209I
S210I: CR29.3(KA) ; port S210I
S211I: CR41.3(KA) ; port S211I
S212I: CR53.3(KA) ; port S212I
S213I: CR65.3(KA) ; port S213I
S214I: CR77.3(KA) ; port S214I
S215I: CR89.3(KA) ; port S215I
S216I: CR101.3(KA) ; port S216I
S217I: CR18.3(KA) ; port S217I
S218I: CR30.3(KA) ; port S218I
S219I: CR42.3(KA) ; port S219I
S220I: CR54.3(KA) ; port S220I
S221I: CR66.3(KA) ; port S221I
S222I: CR78.3(KA) ; port S222I
S223I: CR90.3(KA) ; port S223I
S224I: CR102.3(KA) ; port S224I

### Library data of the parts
CR7-CR102 = D75V0SI16__X: as CR103 on sheet Protection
